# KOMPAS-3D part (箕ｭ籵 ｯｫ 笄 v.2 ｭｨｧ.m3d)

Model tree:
1. Эскиз:1
2. Операция выдавливания:1
     Расстояние 1 = 2
3. Эскиз:2
4. Вырезать элемент выдавливания:2  (labels: Текстолит ГОСТ 5-78; SYSTEM_PROPERTY_ADDITIONAL_FOR:9.000000)
     Расстояние 1 = 2

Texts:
  Центр плата v.2 низ
  Текстолит ГОСТ 5-78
